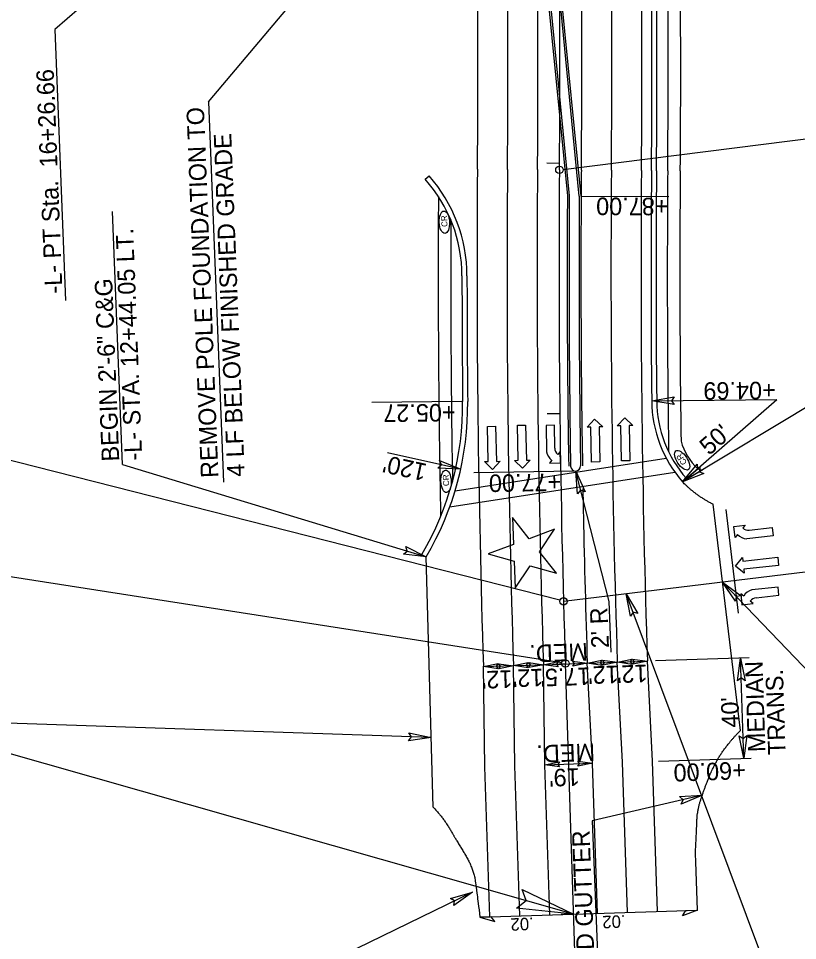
# Model space of a CAD drawing. Extents: x 1627861 to 1629601, y 761281 to 766239.
# Drawn here: x 1628273.7 to 1628584.8, y 761565 to 761933.4 of the extents above; entities that cross this region are included whole.
import ezdxf

# ---------------------------------------------------------------- set-up
doc = ezdxf.new("R2010")
doc.units = 0
for name, color, linetype in [('Exist Property Tie Line Text', 7, 'Continuous'), ('Exist Right of Way Line Leader', 7, 'Continuous'), ('Exist Right of Way Monument Leader', 7, 'Continuous'), ('Exist Right of Way Monument Text', 7, 'Continuous'), ('Exist Utilities Gas Meter CELL', 7, 'Continuous'), ('Exist Utilities Gas Meter Cogo Elevation', 7, 'Continuous'), ('Exist Utilities Gas Meter Cogo Number', 7, 'Continuous'), ('Exist Utilities Gas UG Line', 7, 'Continuous'), ('Exist Utilities Other Unknown UG SUE Text', 7, 'Continuous'), ('Exist Utilities Power UG Cable SUE LOS B Cogo Elevation', 7, 'Continuous'), ('Exist Utilities Power UG Cable SUE LOS B Cogo Point CELL', 7, 'Continuous'), ('Exist Utilities Telephone UG Cable SUE LOS B Cogo Comment', 7, 'Continuous'), ('Exist Utilities Water Fire Hydrant Cogo Elevation', 7, 'Continuous'), ('Exist Utilities Water UG Line SUE LOS B Cogo Number', 7, 'Continuous'), ('Exist Utilities Water Valve CELL', 7, 'Continuous'), ('Scratch_Level_0', 7, 'Continuous'), ('Typical Terminator CELL', 7, 'Continuous')]:
    doc.layers.add(name, color=color, linetype=linetype)

# ---------------------------------------------------------------- blocks, each defined once
blk = doc.blocks.new('Lane Arrow Left Turn')
at = {"layer": 'Exist Right of Way Monument Leader'}
for p, q in [((0, 0), (-4.5, 0.05)), ((-4.5, 0.05), (-3.45, -1)), ((-5.95, -2.15), (-15.1, -2.15)), ((-15.1, -2.15), (-15.1, -5.45)), ((-1.1, -3.35), (-0.05, -4.4)), ((-0.05, -4.4), (0, 0)), ((-15.1, -5.45), (-4.55, -5.45))]:
    blk.add_line(p, q, dxfattribs=at)
for centre, radius, start, end in [((-5.94, 1.11), 3.27, 270, 319.6582), ((-5.34, -0.27), 5.25, 278.6761, 323.9878)]:
    blk.add_arc(centre, radius, start, end, dxfattribs=at)

msp = doc.modelspace()

# ---------------------------------------------------------------- linework, layer by layer
at = {"layer": 'Exist Property Tie Line Text'}
for p, q in [((1628489.77, 761875.49), (1628484.77, 761875.53)), ((1628489.9, 761775.49), (1628484.9, 761775.44)), ((1628492.13, 761675.52), (1628487.13, 761675.36)), ((1628495.4, 761575.57), (1628490.4, 761575.41))]:
    msp.add_line(p, q, dxfattribs=at)
at = {"layer": 'Exist Right of Way Line Leader'}
for p, q in [((1628485.09, 762101.12), (1628288.18, 761928.9)), ((1628288.18, 761928.9), (1628292.45, 761820.66)), ((1628491.24, 761873.08), (1628606.22, 761887.58)), ((1628489.94, 761700.98), (1628222.71, 761768.94)), ((1628490.64, 761675.93), (1628187.22, 761723.24)), ((1628576.79, 761542.18), (1628516.43, 761703.55))]:
    msp.add_line(p, q, dxfattribs=at)
for centre in [(1628489.75, 761872.9), (1628491.37, 761700.53), (1628492.12, 761675.69)]:
    msp.add_circle(centre, 1.5, dxfattribs=at)
at = {"layer": 'Exist Right of Way Monument Leader'}
for p, q in [((1628472.94, 761770.85), (1628476.24, 761770.92)), ((1628473.24, 761756.86), (1628472.94, 761770.85)), ((1628476.24, 761770.92), (1628476.54, 761756.93)), ((1628487.71, 761770.88), (1628484.41, 761770.82)), ((1628487.87, 761761.73), (1628487.71, 761770.88)), ((1628500.78, 761770.13), (1628503.81, 761773.35)), ((1628503.81, 761773.35), (1628507.08, 761770.26)), ((1628512.77, 761770.62), (1628515.8, 761773.83)), ((1628515.8, 761773.83), (1628519.07, 761770.75)), ((1628460.96, 761770.37), (1628464.26, 761770.44)), ((1628461.25, 761756.37), (1628460.96, 761770.37)), ((1628464.26, 761770.44), (1628464.55, 761756.44)), ((1628484.41, 761770.82), (1628484.6, 761760.27)), ((1628502.28, 761770.16), (1628500.78, 761770.13)), ((1628502.58, 761756.16), (1628502.28, 761770.16)), ((1628507.08, 761770.26), (1628505.58, 761770.23)), ((1628505.58, 761770.23), (1628505.88, 761756.24)), ((1628514.27, 761770.65), (1628512.77, 761770.62)), ((1628514.56, 761756.65), (1628514.27, 761770.65)), ((1628519.07, 761770.75), (1628517.57, 761770.72)), ((1628517.57, 761770.72), (1628517.86, 761756.72)), ((1628490.1, 761760.32), (1628489.07, 761759.25)), ((1628490.13, 761755.82), (1628490.1, 761760.32)), ((1628459.76, 761756.34), (1628461.25, 761756.37)), ((1628463.02, 761753.26), (1628459.76, 761756.34)), ((1628466.05, 761756.47), (1628463.02, 761753.26)), ((1628464.55, 761756.44), (1628466.05, 761756.47)), ((1628471.74, 761756.83), (1628473.24, 761756.86)), ((1628475.01, 761753.74), (1628471.74, 761756.83)), ((1628478.04, 761756.96), (1628475.01, 761753.74)), ((1628476.54, 761756.93), (1628478.04, 761756.96)), ((1628486.76, 761756.86), (1628485.73, 761755.79)), ((1628505.88, 761756.24), (1628502.58, 761756.16)), ((1628517.86, 761756.72), (1628514.56, 761756.65)), ((1628485.73, 761755.79), (1628490.13, 761755.82)), ((1628559.43, 761730.46), (1628563.89, 761731.01)), ((1628559.97, 761726.09), (1628559.43, 761730.46)), ((1628563.89, 761731.01), (1628562.97, 761729.85)), ((1628560.89, 761727.25), (1628559.97, 761726.09)), ((1628575.04, 761726.72), (1628564.55, 761725.55)), ((1628565.58, 761728.98), (1628574.67, 761729.99)), ((1628574.67, 761729.99), (1628575.04, 761726.72)), ((1628560.07, 761714.56), (1628562.85, 761718.09)), ((1628562.85, 761718.09), (1628563.01, 761716.6)), ((1628563.01, 761716.6), (1628576.93, 761718.15)), ((1628576.93, 761718.15), (1628577.29, 761714.87)), ((1628563.55, 761711.83), (1628560.07, 761714.56)), ((1628577.29, 761714.87), (1628563.38, 761713.32)), ((1628563.38, 761713.32), (1628563.55, 761711.83))]:
    msp.add_line(p, q, dxfattribs=at)
for centre, radius, start, end in [((1628489.76, 761761.15), 5.25, 189.6847, 234.9964), ((1628491.13, 761761.77), 3.28, 181.0086, 230.6668), ((1628564.77, 761730.78), 5.25, 222.3794, 267.6911), ((1628565.21, 761732.22), 3.27, 226.709, 276.3671)]:
    msp.add_arc(centre, radius, start, end, dxfattribs=at)
at = {"layer": 'Exist Right of Way Monument Text'}
for p, q in [((1628562.05, 761648.93), (1628551.16, 761739.3)), ((1628439.3, 761618.31), (1628436.55, 761718.28))]:
    msp.add_line(p, q, dxfattribs=at)
for points in [[(1628544.86, 761577.19), (1628544.26, 761596.43), (1628544.07, 761599.63)], [(1628457.85, 761575.83), (1628457.9, 761574.35)]]:
    msp.add_lwpolyline(points, dxfattribs=at)
for centre, radius, start, end in [((1623719.93, 761914.16), 4806.75, 359.5044, 1.88553), ((1628392.82, 761830.58), 60, 0.0124, 41.6482), ((1633259.57, 761831.64), 4733.25, 179.5044, 180.61801), ((1633259.57, 761831.64), 4806.75, 180.01243, 180.61106), ((1628333.1, 761779.09), 120, 329.5498, 0.6111), ((1628576.59, 761781.12), 50, 180.618, 221.1523)]:
    msp.add_arc(centre, radius, start, end, dxfattribs=at)
for points in [[(1628551.16, 761739.3), (1628550.58, 761739.58), (1628550.02, 761739.88), (1628549.45, 761740.18), (1628548.89, 761740.48), (1628548.33, 761740.8), (1628547.78, 761741.14), (1628547.23, 761741.47), (1628546.68, 761741.82), (1628546.14, 761742.19), (1628545.59, 761742.55), (1628545.06, 761742.94), (1628544.52, 761743.33), (1628543.57, 761744.05), (1628542.64, 761744.8), (1628541.73, 761745.58), (1628540.85, 761746.34), (1628540, 761747.13), (1628539.19, 761747.97), (1628539.11, 761748.06), (1628539.03, 761748.14), (1628538.95, 761748.22)], [(1628544.07, 761599.63), (1628544.27, 761604.16), (1628544.47, 761608.7), (1628544.66, 761613.24), (1628544.72, 761614.53), (1628544.89, 761615.81), (1628545.13, 761617.09), (1628545.36, 761618.37), (1628545.68, 761619.63), (1628546.07, 761620.87), (1628546.47, 761622.12), (1628546.87, 761623.37), (1628547.32, 761624.6), (1628547.55, 761625.22), (1628547.78, 761625.84), (1628548.01, 761626.46), (1628548.24, 761627.08), (1628548.48, 761627.7), (1628548.71, 761628.32), (1628548.98, 761629.03), (1628549.27, 761629.74), (1628549.55, 761630.44), (1628549.83, 761631.14), (1628550.14, 761631.83), (1628550.45, 761632.51), (1628551.07, 761633.87), (1628551.74, 761635.2), (1628552.46, 761636.51), (1628553.19, 761637.82), (1628553.98, 761639.09), (1628554.82, 761640.33), (1628555.24, 761640.96), (1628555.68, 761641.59), (1628556.14, 761642.19), (1628556.61, 761642.81), (1628557.09, 761643.42), (1628557.58, 761644.02), (1628558.29, 761644.88), (1628559.01, 761645.73), (1628559.76, 761646.55), (1628560.51, 761647.36), (1628561.26, 761648.16), (1628562.05, 761648.93)], [(1628439.3, 761618.31), (1628440.23, 761617.33), (1628441.13, 761616.32), (1628441.99, 761615.28), (1628442.99, 761614.08), (1628443.9, 761612.81), (1628444.75, 761611.5), (1628445.17, 761610.85), (1628445.59, 761610.2), (1628445.98, 761609.53), (1628446.38, 761608.86), (1628446.78, 761608.18), (1628447.17, 761607.51), (1628447.4, 761607.13), (1628447.63, 761606.74), (1628447.85, 761606.36), (1628448.08, 761605.98), (1628448.31, 761605.6), (1628448.54, 761605.22), (1628449.01, 761604.45), (1628449.48, 761603.69), (1628449.95, 761602.93), (1628450.88, 761601.41), (1628451.77, 761599.87), (1628452.66, 761598.32), (1628453.54, 761596.8), (1628454.27, 761595.22), (1628454.88, 761593.56), (1628455.48, 761591.92), (1628455.95, 761590.25), (1628456.17, 761588.53), (1628456.73, 761584.3), (1628457.29, 761580.06), (1628457.85, 761575.83)]]:
    msp.add_open_spline(points, degree=3, dxfattribs=at)
at = {"layer": 'Exist Utilities Gas Meter CELL'}
for p, q in [((1628626.11, 761716.77), (1628491.37, 761700.53)), ((1628501.93, 761375.68), (1628492.12, 761675.69))]:
    msp.add_line(p, q, dxfattribs=at)
for centre, start, end in [((1623719.93, 761914.16), 359.5044, 2.25819), ((1633259.57, 761831.64), 179.5044, 181.87347)]:
    msp.add_arc(centre, 4770, start, end, dxfattribs=at)
at = {"layer": 'Exist Utilities Gas Meter Cogo Elevation'}
for p, q in [((1628436.16, 761869.13), (1628437.66, 761870.45)), ((1628538.95, 761748.22), (1628540.45, 761749.54))]:
    msp.add_line(p, q, dxfattribs=at)
for centre, radius, start, end in [((1623719.93, 761914.16), 4808.75, 359.5044, 1.88551), ((1633259.57, 761831.64), 4731.25, 179.5044, 180.61801), ((1628392.82, 761830.58), 58, 0.0124, 41.6482), ((1633259.57, 761831.64), 4808.75, 180.01243, 180.61106), ((1628333.1, 761779.09), 118, 329.5498, 0.6111), ((1628576.59, 761781.12), 48, 180.618, 221.1523)]:
    msp.add_arc(centre, radius, start, end, dxfattribs=at)
at = {"layer": 'Exist Utilities Gas Meter Cogo Number'}
for points in [[(1628535.61, 761779.13), (1628526.6, 761780.58), (1628535.63, 761782.28), (1628534.5, 761780.67)], [(1628441.85, 761756.82), (1628450.31, 761753.38), (1628441.13, 761753.76), (1628442.6, 761755.07)], [(1628496.98, 761743.49), (1628496.25, 761752.59), (1628500.05, 761744.23), (1628498.21, 761744.94)], [(1628546.74, 761752.98), (1628538.95, 761748.22), (1628544.71, 761755.38), (1628544.89, 761753.42)], [(1628547.45, 761751.55), (1628538.95, 761748.22), (1628545.86, 761754.27), (1628545.71, 761752.31)], [(1628428.39, 761722.38), (1628436.55, 761718.28), (1628427.43, 761719.38), (1628428.99, 761720.58)], [(1628560.01, 761700.61), (1628554.9, 761708.18), (1628562.32, 761702.75), (1628560.37, 761702.48)], [(1628518.13, 761694.58), (1628516.43, 761703.55), (1628521.1, 761695.63), (1628519.19, 761696.15)], [(1628465.27, 761673.6), (1628459.39, 761674.45), (1628465.25, 761675.65), (1628464.53, 761674.59)], [(1628465.51, 761675.62), (1628471.39, 761674.77), (1628465.54, 761673.57), (1628466.26, 761674.63)], [(1628477.26, 761673.99), (1628471.39, 761674.84), (1628477.24, 761676.04), (1628476.52, 761674.98)], [(1628477.51, 761676.09), (1628483.38, 761675.23), (1628477.53, 761674.04), (1628478.25, 761675.1)], [(1628489.26, 761674.38), (1628483.38, 761675.23), (1628489.23, 761676.43), (1628488.51, 761675.37)], [(1628494.99, 761676.62), (1628500.87, 761675.81), (1628495.03, 761674.57), (1628495.74, 761675.64)], [(1628506.75, 761674.96), (1628500.87, 761675.81), (1628506.72, 761677), (1628506, 761675.94)], [(1628506.99, 761677.05), (1628512.87, 761676.2), (1628507.01, 761675), (1628507.73, 761676.06)], [(1628518.74, 761675.35), (1628512.87, 761676.2), (1628518.72, 761677.4), (1628518, 761676.34)], [(1628518.98, 761677.44), (1628524.86, 761676.59), (1628519.01, 761675.39), (1628519.73, 761676.45)], [(1628560.83, 761668.76), (1628562.09, 761677.81), (1628563.98, 761668.82), (1628562.35, 761669.91)], [(1628429.59, 761647.94), (1628438.54, 761646.09), (1628429.44, 761644.8), (1628430.64, 761646.36)], [(1628564.65, 761646.88), (1628563.4, 761637.83), (1628561.5, 761646.82), (1628563.14, 761645.73)], [(1628489.81, 761634.38), (1628483.94, 761635.23), (1628489.79, 761636.43), (1628489.07, 761635.37)], [(1628497.05, 761636.7), (1628502.93, 761635.85), (1628497.08, 761634.66), (1628497.8, 761635.72)], [(1628537.73, 761622.56), (1628546.85, 761623.08), (1628538.39, 761619.48), (1628539.15, 761621.3)], [(1628446.2, 761581.82), (1628454.97, 761584.36), (1628447.53, 761578.96), (1628447.86, 761580.9)], [(1628474.81, 761585.46), (1628495.4, 761575.57), (1628472.54, 761577.92), (1628476.4, 761580.98)]]:
    msp.add_lwpolyline(points, close=True, dxfattribs=at)
at = {"layer": 'Exist Utilities Gas UG Line'}
for p, q in [((1628480.61, 761987.35), (1628492.92, 761862.47)), ((1628498.42, 761862.44), (1628486.11, 761987.44)), ((1628483.94, 761635.23), (1628483.38, 761675.41)), ((1628502.93, 761635.85), (1628500.87, 761675.98)), ((1628514.92, 761636.24), (1628512.86, 761676.37)), ((1628526.92, 761636.64), (1628524.85, 761676.77)), ((1628459.95, 761634.45), (1628459.39, 761674.62)), ((1628471.95, 761634.84), (1628471.38, 761675.02)), ((1628473.91, 761574.87), (1628471.95, 761634.84)), ((1628485.9, 761575.26), (1628483.94, 761635.23)), ((1628504.89, 761575.88), (1628502.93, 761635.85)), ((1628516.88, 761576.28), (1628514.92, 761636.24)), ((1628528.88, 761576.67), (1628526.92, 761636.64)), ((1628461.91, 761574.48), (1628459.95, 761634.45))]:
    msp.add_line(p, q, dxfattribs=at)
for centre, radius, start, end in [((1623719.93, 761914.16), 4749.25, 359.5044, 1.96193), ((1623719.93, 761914.16), 4790.75, 359.5044, 1.96193), ((1623719.93, 761914.16), 4802.75, 359.5044, 1.96193), ((1623719.93, 761914.16), 4737.25, 359.5044, 1.96193), ((1623719.93, 761914.16), 4778.75, 359.5044, 1.93871), ((1623719.93, 761914.16), 4761.25, 359.5044, 0.88088), ((1633259.57, 761831.64), 4802.75, 179.5044, 181.87347), ((1633259.57, 761831.64), 4790.75, 179.5044, 181.87347), ((1633259.57, 761831.64), 4778.75, 179.5044, 181.87347), ((1633259.57, 761831.64), 4761.25, 179.5044, 179.62938), ((1633259.57, 761831.64), 4749.25, 179.5044, 181.87347), ((1633259.57, 761831.64), 4737.25, 179.5044, 181.87347), ((1633259.57, 761831.64), 4766.75, 179.62938, 180.92664), ((1633259.57, 761831.64), 4761.25, 179.62938, 180.92664), ((1633259.57, 761831.64), 4761.25, 181.03475, 181.16689), ((1633259.57, 761831.64), 4761.25, 181.16689, 181.87347)]:
    msp.add_arc(centre, radius, start, end, dxfattribs=at)
at = {"layer": 'Exist Utilities Other Unknown UG SUE Text'}
for p, q in [((1628481.36, 761987.37), (1628493.67, 761862.47)), ((1628497.67, 761862.44), (1628485.36, 761987.43))]:
    msp.add_line(p, q, dxfattribs=at)
for centre, radius, start, end in [((1633259.57, 761831.64), 4766, 179.62938, 180.92664), ((1633259.57, 761831.64), 4762, 179.62938, 180.92664), ((1628496.19, 761754.59), 2, 182.2582, 0.9265)]:
    msp.add_arc(centre, radius, start, end, dxfattribs=at)
at = {"layer": 'Exist Utilities Power UG Cable SUE LOS B Cogo Elevation'}
msp.add_lwpolyline([(1628471.65, 761716.54), (1628472.08, 761705.74), (1628478.08, 761714.73), (1628488.51, 761711.79), (1628481.8, 761720.3), (1628487.81, 761729.31), (1628477.66, 761725.55), (1628470.95, 761734.05), (1628471.38, 761723.24), (1628461.22, 761719.48), (1628471.65, 761716.54)], dxfattribs=at)
at = {"layer": 'Exist Utilities Telephone UG Cable SUE LOS B Cogo Comment'}
for p, q in [((1628448.04, 761744.62), (1628532.43, 761757.68)), ((1628445.92, 761738.22), (1628535.85, 761752.14)), ((1628556.19, 761737.21), (1628561.18, 761695.8))]:
    msp.add_line(p, q, dxfattribs=at)
at = {"layer": 'Exist Utilities Water Fire Hydrant Cogo Elevation'}
for centre, major_axis in [((1628443.79, 761851.97), (-0.18, 4.48)), ((1628538.76, 761756.88), (-2.48, 3.73)), ((1628444.46, 761748.46), (-0.18, 4.48))]:
    msp.add_ellipse(centre, major_axis=major_axis, ratio=0.462467, dxfattribs=at)
at = {"layer": 'Exist Utilities Water UG Line SUE LOS B Cogo Number'}
msp.add_line((1628457.92, 761574.35), (1628544.87, 761577.19), dxfattribs=at)
at = {"layer": 'Exist Utilities Water Valve CELL'}
msp.add_line((1628538.95, 761748.22), (1628544.96, 761753.48), dxfattribs=at)
for centre, radius, start, end in [((1623719.93, 761914.16), 4813.25, 359.5044, 1.28119), ((1623719.93, 761914.16), 4818.25, 359.5044, 1.2786), ((1633259.57, 761831.64), 4726.75, 179.5044, 180.86511), ((1633259.57, 761831.64), 4721.75, 179.5044, 180.81451), ((1633259.57, 761831.64), 4818.25, 179.63608, 181.15656), ((1633259.57, 761831.64), 4813.25, 179.74726, 180.99082), ((1628562.16, 761771.4), 24.83, 196.0904, 226.1797)]:
    msp.add_arc(centre, radius, start, end, dxfattribs=at)
at = {"layer": 'Scratch_Level_0'}
for p, q in [((1628349.57, 761900.08), (1628501.04, 762080.06)), ((1628349.57, 761900.08), (1628355.56, 761748.11)), ((1628498.42, 761862.44), (1628533.42, 761862.28)), ((1628315.28, 761755.19), (1628311.29, 761856.24)), ((1628657.43, 761819.78), (1628538.95, 761748.22)), ((1628450.7, 761780.35), (1628414.78, 761779.97)), ((1628526.6, 761780.58), (1628576.59, 761781.12)), ((1628538.95, 761748.22), (1628576.59, 761781.12)), ((1628450.31, 761753.38), (1628421.04, 761759.8)), ((1628315.28, 761755.19), (1628436.55, 761718.28)), ((1628495.51, 761752.58), (1628455.61, 761751.92)), ((1628509.63, 761700.43), (1628496.25, 761752.59)), ((1628554.9, 761708.18), (1628623.54, 761636.44)), ((1628510.43, 761680.18), (1628509.63, 761700.43)), ((1628471.39, 761674.84), (1628483.38, 761675.23)), ((1628483.38, 761675.23), (1628500.87, 761675.81)), ((1628500.87, 761675.81), (1628512.87, 761676.2)), ((1628512.87, 761676.2), (1628524.86, 761676.59)), ((1628565.57, 761677.92), (1628528.06, 761676.7)), ((1628563.4, 761637.83), (1628562.09, 761677.81)), ((1628459.39, 761674.45), (1628471.39, 761674.84)), ((1628438.54, 761646.09), (1628200.87, 761654.13)), ((1628495.4, 761575.57), (1628247.94, 761645.94)), ((1628483.94, 761635.23), (1628502.93, 761635.85)), ((1628529.37, 761636.72), (1628566.35, 761637.93)), ((1628546.85, 761623.08), (1628502.85, 761612.9)), ((1628502.85, 761612.9), (1628509.86, 761435.2)), ((1628454.97, 761584.36), (1628398.39, 761556.83))]:
    msp.add_line(p, q, dxfattribs=at)
at = {"layer": 'Typical Terminator CELL'}
for points in [[(1628544.87, 761577.19), (1628538.95, 761574.96), (1628540.25, 761577.01)], [(1628457.92, 761574.35), (1628463.99, 761572.59), (1628462.54, 761574.53)]]:
    msp.add_lwpolyline(points, close=True, dxfattribs=at)

# ---------------------------------------------------------------- block references
at = {"layer": 'Exist Right of Way Monument Leader', "rotation": -173.69913645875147}
msp.add_blockref('Lane Arrow Left Turn', (1628562.65, 761699.18), dxfattribs=at)

# ---------------------------------------------------------------- texts
at = {"layer": 'Exist Right of Way Line Leader'}
msp.add_text('-L- PT Sta.  16+26.66', height=7, rotation=92.2582, dxfattribs=at).set_placement((1628291.29, 761823.58))
at = {"layer": 'Exist Utilities Power UG Cable SUE LOS B Cogo Point CELL'}
for s, rotation, p in [('REMOVE POLE FOUNDATION TO', 92.2582, (1628353.58, 761749.99)), ('4 LF BELOW FINISHED GRADE', 92.2582, (1628364.07, 761750.4)), ('-L- STA. 12+44.05 LT.', 92.2582, (1628323.13, 761756.88)), ('BEGIN 2\'-6" C&G', 92.2582, (1628313.96, 761756.52)), ('+04.69', 180.618, (1628576.1, 761788.33)), ('+05.27', 180.6111, (1628448.24, 761779.45)), ("50'", 41.1523, (1628549.51, 761758.54)), ("120'", 167.6263, (1628437.19, 761755.32)), ('MED.', 182.0586, (1628501, 761683.9)), ("12'", 182.0586, (1628524.82, 761675.3)), ("12'", 182.0586, (1628470.83, 761673.06)), ("12'", 182.0586, (1628483.19, 761673.65)), ("17.5'", 182.0586, (1628502.04, 761674.18)), ("12'", 182.0586, (1628513.28, 761674.92)), ('MED.', 182.0586, (1628503.83, 761643.84)), ('+60.00', 182.0586, (1628564.05, 761636.54)), ("19'", 182.0586, (1628497.7, 761633.92)), ('RETAIN EXISTING CURB AND GUTTER', 92.2582, (1628508.55, 761436.14))]:
    msp.add_text(s, height=7, rotation=rotation, dxfattribs=at).set_placement(p)
at = {"layer": 'Exist Utilities Water Fire Hydrant Cogo Elevation'}
for rotation, p in [(92.2582, (1628445.05, 761850.14)), (123.6369, (1628540.79, 761755.96)), (92.2582, (1628445.71, 761746.63))]:
    msp.add_text('CR', height=2.4, rotation=rotation, dxfattribs=at).set_placement(p)
at = {"layer": 'Exist Utilities Water UG Line SUE LOS B Cogo Number'}
for p in [(1628479.4, 761574.26), (1628516.04, 761575.21)]:
    msp.add_text('.02', height=5, rotation=182.2582, dxfattribs=at).set_placement(p)
at = {"layer": 'Scratch_Level_0'}
for s, rotation, p in [('+87.00', 179.7495, (1628533.31, 761861.72)), ('+77.00', 180.9507, (1628490.4, 761751.65)), ("2' R", 92.2582, (1628509.53, 761681.94)), ('MEDIAN', 91.8735, (1628572.05, 761640.42)), (' TRANS.', 91.8735, (1628580.2, 761636.67)), ("40' ", 91.8735, (1628561.6, 761650.2))]:
    msp.add_text(s, height=7, rotation=rotation, dxfattribs=at).set_placement(p)

doc.saveas('drawing.dxf')
